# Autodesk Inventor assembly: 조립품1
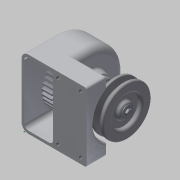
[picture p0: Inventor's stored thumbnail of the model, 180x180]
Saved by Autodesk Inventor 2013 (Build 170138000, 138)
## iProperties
Created: 2015-02
Part Number: 조립품1
Document SubType Name: Assembly
Designer: Administrator
Author: Administrator
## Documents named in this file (14)
- C:\Users\Administrator\Desktop\450216V1025\조립품1.iam
- C:\Users\Administrator\Desktop\450216V1025\본체.ipt
- C:\Users\Administrator\Desktop\450216V1025\축.ipt
- C:\Users\Administrator\Desktop\450216V1025\베어링 6001.ipt
- C:\Users\Administrator\Desktop\450216V1025\키5x5.ipt
- C:\Users\Administrator\Desktop\450216V1025\스퍼기어.ipt
- C:\Users\Administrator\Desktop\450216V1025\오일실.ipt
- C:\Users\Administrator\Desktop\450216V1025\축커버.ipt
- C:\Users\Administrator\Desktop\450216V1025\M3x0.5.ipt
- C:\Users\Administrator\Desktop\450216V1025\V-벨트풀리.ipt
- C:\Users\Administrator\Desktop\450216V1025\키4x4.ipt
- C:\Users\Administrator\Desktop\450216V1025\와샤.ipt
- C:\Users\Administrator\Desktop\450216V1025\M5x0.8.ipt
- M5x0.8.ipt
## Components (6 placed, 3 different names)
1. M3x0.5:1
2. M3x0.5:2
3. M3x0.5:3
4. M3x0.5:4
5. V-벨트풀리:1
6. M5x0.8:1
